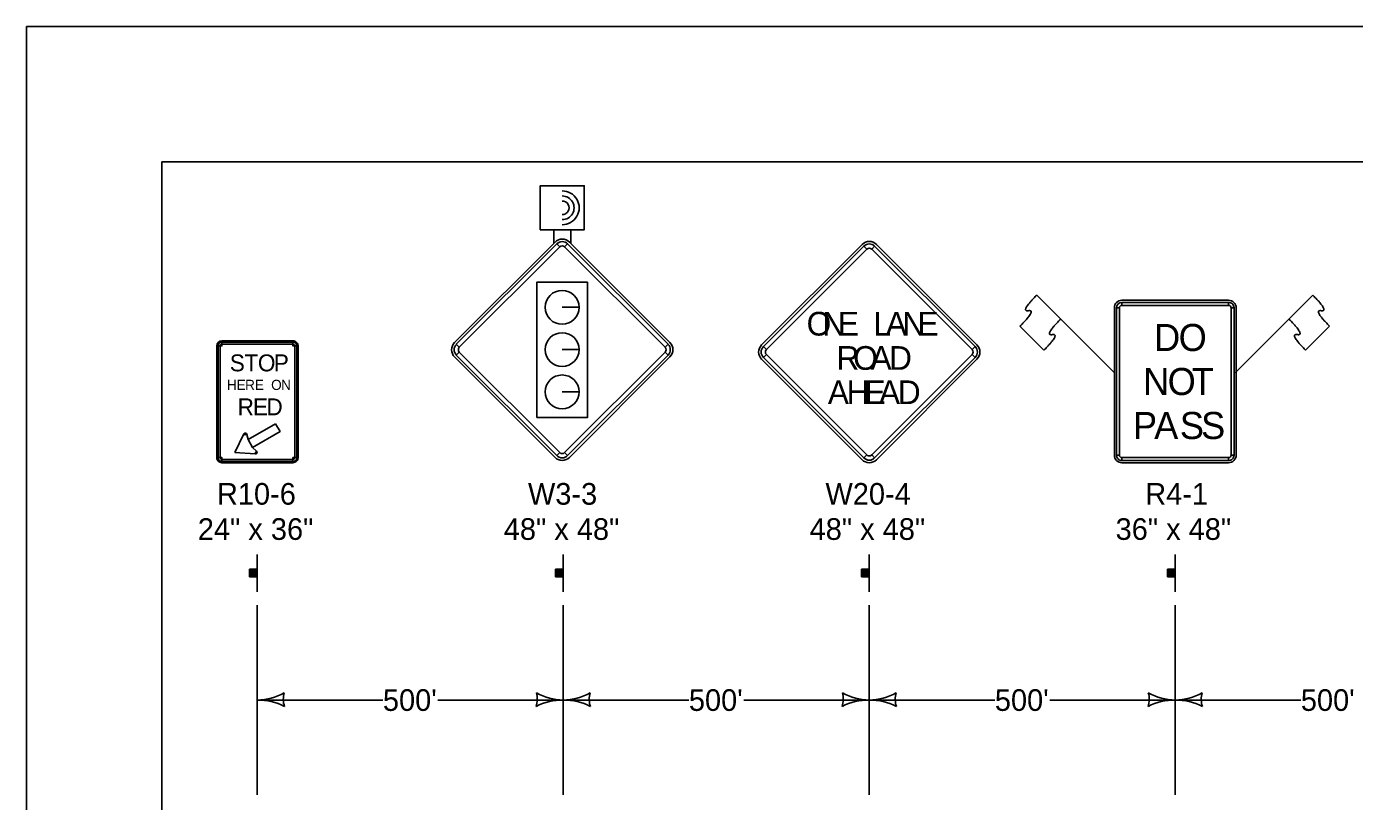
# Model space of a CAD drawing. Extents: x -2134934 to -2122394, y -2139046 to -2137036.
# Drawn here: x -2125529 to -2124549, y -2137608 to -2137036 of the extents above; entities that cross this region are included whole.
import ezdxf

# ---------------------------------------------------------------- set-up
doc = ezdxf.new("R2010")
doc.units = 0
for name, color, linetype in [('Barrier', 7, 'Continuous'), ('BridgeSuperStructureExisting', 7, 'Continuous'), ('Default', 7, 'Continuous'), ('TC_Barrier', 7, 'Continuous')]:
    doc.layers.add(name, color=color, linetype=linetype)

msp = doc.modelspace()

# ---------------------------------------------------------------- linework, layer by layer
at = {"layer": 'Barrier'}
for p, q in [((-2125139.05, -2137195.1), (-2125213.3, -2137269.35)), ((-2125137.72, -2137196.43), (-2125135.52, -2137198.64)), ((-2125131.98, -2137198.64), (-2125129.77, -2137196.43)), ((-2125054.2, -2137269.35), (-2125128.44, -2137195.1)), ((-2124912.21, -2137196.82), (-2124986.46, -2137271.07)), ((-2124910.89, -2137198.15), (-2124908.68, -2137200.36)), ((-2124905.14, -2137200.36), (-2124902.93, -2137198.15)), ((-2124827.36, -2137271.07), (-2124901.61, -2137196.82)), ((-2125121.34, -2137243.32), (-2125133.84, -2137243.32)), ((-2125133.84, -2137243.32), (-2125121.34, -2137243.32)), ((-2124725.87, -2137291.63), (-2124783.21, -2137234.33)), ((-2124783.21, -2137234.33), (-2124765.52, -2137252.01)), ((-2124641.5, -2137238.12), (-2124720.25, -2137238.12)), ((-2124720.25, -2137241.87), (-2124720.25, -2137239.68)), ((-2124641.5, -2137239.68), (-2124641.5, -2137241.87)), ((-2124636.58, -2137291.63), (-2124579.26, -2137234.32)), ((-2124579.26, -2137234.32), (-2124596.94, -2137252)), ((-2124725.87, -2137243.74), (-2124725.87, -2137352.49)), ((-2124724.31, -2137243.74), (-2124722.12, -2137243.74)), ((-2124639.62, -2137243.74), (-2124637.43, -2137243.74)), ((-2124635.87, -2137352.49), (-2124635.87, -2137243.74)), ((-2124777.9, -2137275), (-2124795.58, -2137257.33)), ((-2124584.56, -2137274.99), (-2124566.88, -2137257.31)), ((-2125388.89, -2137271.87), (-2125385.14, -2137271.87)), ((-2125387.95, -2137271.87), (-2125386.39, -2137271.87)), ((-2125385.14, -2137271.87), (-2125385.14, -2137268.12)), ((-2125385.14, -2137270.62), (-2125385.14, -2137269.05)), ((-2125332.64, -2137268.12), (-2125332.64, -2137271.87)), ((-2125332.64, -2137269.05), (-2125332.64, -2137270.62)), ((-2125332.64, -2137271.87), (-2125328.89, -2137271.87)), ((-2125331.39, -2137271.87), (-2125329.82, -2137271.87)), ((-2125209.76, -2137272.88), (-2125211.97, -2137270.67)), ((-2125055.53, -2137270.67), (-2125057.73, -2137272.88)), ((-2124982.92, -2137274.6), (-2124985.13, -2137272.39)), ((-2124828.69, -2137272.39), (-2124830.89, -2137274.6)), ((-2125213.3, -2137279.95), (-2125139.05, -2137354.2)), ((-2125211.97, -2137278.63), (-2125209.76, -2137276.42)), ((-2125121.34, -2137274.57), (-2125133.84, -2137274.57)), ((-2125133.84, -2137274.57), (-2125121.34, -2137274.57)), ((-2125128.44, -2137354.2), (-2125054.2, -2137279.95)), ((-2125057.73, -2137276.42), (-2125055.53, -2137278.63)), ((-2124986.46, -2137281.67), (-2124912.21, -2137355.92)), ((-2124985.13, -2137280.35), (-2124982.92, -2137278.14)), ((-2124901.61, -2137355.92), (-2124827.36, -2137281.67)), ((-2124830.89, -2137278.14), (-2124828.69, -2137280.35)), ((-2125121.34, -2137305.82), (-2125133.84, -2137305.82)), ((-2125133.84, -2137305.82), (-2125121.34, -2137305.82)), ((-2125369.03, -2137336.85), (-2125367.92, -2137337.43)), ((-2125367.92, -2137337.43), (-2125366.7, -2137337.16)), ((-2125360.42, -2137350.42), (-2125360.47, -2137351.67)), ((-2125359.58, -2137349.5), (-2125360.42, -2137350.42)), ((-2125135.52, -2137350.66), (-2125137.72, -2137352.87)), ((-2125129.77, -2137352.87), (-2125131.98, -2137350.66)), ((-2125385.14, -2137354.37), (-2125388.89, -2137354.37)), ((-2125386.39, -2137354.37), (-2125387.95, -2137354.37)), ((-2125385.14, -2137358.12), (-2125385.14, -2137354.37)), ((-2125385.14, -2137357.18), (-2125385.14, -2137355.62)), ((-2125328.89, -2137354.37), (-2125332.64, -2137354.37)), ((-2125332.64, -2137354.37), (-2125332.64, -2137358.12)), ((-2125332.64, -2137355.62), (-2125332.64, -2137357.18)), ((-2125329.82, -2137354.37), (-2125331.39, -2137354.37)), ((-2124908.68, -2137352.38), (-2124910.89, -2137354.59)), ((-2124902.93, -2137354.59), (-2124905.14, -2137352.38)), ((-2124722.12, -2137352.49), (-2124724.31, -2137352.49)), ((-2124720.25, -2137356.55), (-2124720.25, -2137354.37)), ((-2124720.25, -2137358.12), (-2124641.5, -2137358.12)), ((-2124641.5, -2137354.37), (-2124641.5, -2137356.55)), ((-2124637.43, -2137352.49), (-2124639.62, -2137352.49))]:
    msp.add_line(p, q, dxfattribs=at)
for points in [[(-2125429.46, -2137135.95), (-2124308.22, -2137135.95), (-2124308.22, -2137986.59), (-2125429.46, -2137986.59)], [(-2125137.72, -2137196.43), (-2125211.97, -2137270.67), (-2125209.76, -2137272.88), (-2125135.52, -2137198.64), (-2125137.72, -2137196.43)], [(-2125055.53, -2137270.67), (-2125129.77, -2137196.43), (-2125131.98, -2137198.64), (-2125057.73, -2137272.88), (-2125055.53, -2137270.67)], [(-2124910.89, -2137198.15), (-2124985.13, -2137272.39), (-2124982.92, -2137274.6), (-2124908.68, -2137200.36), (-2124910.89, -2137198.15)], [(-2124828.69, -2137272.39), (-2124902.93, -2137198.15), (-2124905.14, -2137200.36), (-2124830.89, -2137274.6), (-2124828.69, -2137272.39)], [(-2125115.02, -2137224.71), (-2125152.48, -2137224.71), (-2125152.48, -2137324.6), (-2125115.02, -2137324.6), (-2125115.02, -2137224.71)], [(-2124641.5, -2137239.68), (-2124720.25, -2137239.68), (-2124720.25, -2137241.87), (-2124641.5, -2137241.87), (-2124641.5, -2137239.68)], [(-2124724.31, -2137243.74), (-2124724.31, -2137352.49), (-2124722.12, -2137352.49), (-2124722.12, -2137243.74), (-2124724.31, -2137243.74)], [(-2124637.43, -2137352.49), (-2124637.43, -2137243.74), (-2124639.62, -2137243.74), (-2124639.62, -2137352.49), (-2124637.43, -2137352.49)], [(-2125385.14, -2137358.12), (-2125332.64, -2137358.12), (-2125332.64, -2137354.37), (-2125328.89, -2137354.37), (-2125328.89, -2137271.87), (-2125332.64, -2137271.87), (-2125332.64, -2137268.12), (-2125385.14, -2137268.12), (-2125385.14, -2137271.87), (-2125388.89, -2137271.87), (-2125388.89, -2137354.37), (-2125385.14, -2137354.37), (-2125385.14, -2137358.12)], [(-2125386.39, -2137271.87), (-2125386.39, -2137354.37), (-2125387.95, -2137354.37), (-2125387.95, -2137271.87), (-2125386.39, -2137271.87)], [(-2125332.64, -2137270.62), (-2125385.14, -2137270.62), (-2125385.14, -2137269.05), (-2125332.64, -2137269.05), (-2125332.64, -2137270.62)], [(-2125331.39, -2137354.37), (-2125331.39, -2137271.87), (-2125329.82, -2137271.87), (-2125329.82, -2137354.37), (-2125331.39, -2137354.37)], [(-2125211.97, -2137278.63), (-2125137.72, -2137352.87), (-2125135.52, -2137350.66), (-2125209.76, -2137276.42), (-2125211.97, -2137278.63)], [(-2125129.77, -2137352.87), (-2125055.53, -2137278.63), (-2125057.73, -2137276.42), (-2125131.98, -2137350.66), (-2125129.77, -2137352.87)], [(-2124985.13, -2137280.35), (-2124910.89, -2137354.59), (-2124908.68, -2137352.38), (-2124982.92, -2137278.14), (-2124985.13, -2137280.35)], [(-2124902.93, -2137354.59), (-2124828.69, -2137280.35), (-2124830.89, -2137278.14), (-2124905.14, -2137352.38), (-2124902.93, -2137354.59)], [(-2125345.52, -2137329.37), (-2125342.23, -2137335.05), (-2125362.54, -2137346.77), (-2125365.82, -2137341.09), (-2125345.52, -2137329.37)], [(-2125375.54, -2137350.49), (-2125360.47, -2137351.67), (-2125360.42, -2137350.42), (-2125359.58, -2137349.5), (-2125362.54, -2137346.77), (-2125365.82, -2137341.09), (-2125366.7, -2137337.16), (-2125367.92, -2137337.43), (-2125369.03, -2137336.85), (-2125375.54, -2137350.49)], [(-2125385.14, -2137355.62), (-2125332.64, -2137355.62), (-2125332.64, -2137357.18), (-2125385.14, -2137357.18), (-2125385.14, -2137355.62)], [(-2124720.25, -2137356.55), (-2124641.5, -2137356.55), (-2124641.5, -2137354.37), (-2124720.25, -2137354.37), (-2124720.25, -2137356.55)]]:
    msp.add_lwpolyline(points, close=True, dxfattribs=at)
for centre in [(-2125133.84, -2137243.32), (-2125133.84, -2137274.57), (-2125133.84, -2137305.82)]:
    msp.add_circle(centre, 12.5, dxfattribs=at)
for centre, radius, start, end in [((-2125133.75, -2137200.41), 7.5, 44.99999, 134.99974), ((-2124906.91, -2137202.12), 7.5, 44.99999, 134.99974), ((-2125133.75, -2137200.41), 5.62, 44.99999, 134.99974), ((-2125133.75, -2137200.41), 2.5, 44.99999, 134.99974), ((-2124906.91, -2137202.12), 5.62, 44.99999, 134.99974), ((-2124906.91, -2137202.12), 2.5, 44.99999, 134.99974), ((-2124720.25, -2137243.74), 5.62, 90.00021, 179.99985), ((-2124720.25, -2137243.74), 4.06, 90.00021, 179.99985), ((-2124720.25, -2137243.74), 1.87, 90.00021, 179.99985), ((-2124641.5, -2137243.74), 5.62, 0, 90.00021), ((-2124641.5, -2137243.74), 4.06, 0, 90.00021), ((-2124641.5, -2137243.74), 1.87, 0, 90.00021), ((-2125385.14, -2137271.87), 3.75, 90.00021, 179.99985), ((-2125385.14, -2137271.87), 2.81, 90.00021, 179.99985), ((-2125385.14, -2137271.87), 1.25, 90.00021, 179.99985), ((-2125332.64, -2137271.87), 3.75, 0, 90.00021), ((-2125332.64, -2137271.87), 2.81, 0, 90.00021), ((-2125332.64, -2137271.87), 1.25, 0, 90.00021), ((-2125207.99, -2137274.65), 7.5, 134.99974, 224.99995), ((-2125207.99, -2137274.65), 5.62, 134.99974, 224.99995), ((-2125207.99, -2137274.65), 2.5, 134.99974, 224.99995), ((-2125059.5, -2137274.65), 2.5, 315.00016, 44.9998), ((-2125059.5, -2137274.65), 5.62, 315.00016, 44.9998), ((-2125059.5, -2137274.65), 7.5, 315.00016, 44.9998), ((-2124981.15, -2137276.37), 7.5, 134.99974, 224.99995), ((-2124981.15, -2137276.37), 5.62, 134.99974, 224.99995), ((-2124832.66, -2137276.37), 5.62, 315.00016, 44.9998), ((-2124832.66, -2137276.37), 7.5, 315.00016, 44.9998), ((-2124981.15, -2137276.37), 2.5, 134.99974, 224.99995), ((-2124832.66, -2137276.37), 2.5, 315.00016, 44.9998), ((-2125367.92, -2137337.43), 1.25, 12.62232, 152.27557), ((-2125360.42, -2137350.42), 1.25, 267.72427, 47.37758), ((-2125133.75, -2137348.9), 2.5, 224.99995, 315.00016), ((-2125385.14, -2137354.37), 3.75, 179.99985, 270.00006), ((-2125385.14, -2137354.37), 2.81, 179.99985, 270.00006), ((-2125385.14, -2137354.37), 1.25, 179.99985, 270.00006), ((-2125332.64, -2137354.37), 3.75, 270.00006, 0.00027), ((-2125332.64, -2137354.37), 2.81, 270.00006, 0.00027), ((-2125332.64, -2137354.37), 1.25, 270.00006, 0.00027), ((-2125133.75, -2137348.9), 7.5, 224.99995, 315.00016), ((-2125133.75, -2137348.9), 5.62, 224.99995, 315.00016), ((-2124906.91, -2137350.62), 7.5, 224.99995, 315.00016), ((-2124906.91, -2137350.62), 5.62, 224.99995, 315.00016), ((-2124906.91, -2137350.62), 2.5, 224.99995, 315.00016), ((-2124720.25, -2137352.49), 5.62, 179.99985, 270.00006), ((-2124720.25, -2137352.49), 4.06, 179.99985, 270.00006), ((-2124720.25, -2137352.49), 1.87, 179.99985, 270.00006), ((-2124641.5, -2137352.49), 5.62, 270.00006, 0.00027), ((-2124641.5, -2137352.49), 4.06, 270.00006, 0.00027), ((-2124641.5, -2137352.49), 1.87, 270.00006, 0.00027)]:
    msp.add_arc(centre, radius, start, end, dxfattribs=at)
for points in [[(-2124795.58, -2137257.33), (-2124783.21, -2137244.95), (-2124795.58, -2137246.72), (-2124783.21, -2137234.33)], [(-2124566.88, -2137257.31), (-2124579.26, -2137244.93), (-2124566.88, -2137246.7), (-2124579.26, -2137234.32)], [(-2124765.52, -2137252.01), (-2124777.89, -2137264.4), (-2124765.53, -2137262.62), (-2124777.9, -2137275)], [(-2124596.94, -2137252), (-2124584.56, -2137264.38), (-2124596.93, -2137262.61), (-2124584.56, -2137274.99)]]:
    msp.add_open_spline(points, degree=2, dxfattribs=at)
at = {"layer": 'BridgeSuperStructureExisting'}
for p, q in [((-2125139.98, -2137186.06), (-2125139.98, -2137196.06)), ((-2125127.48, -2137186.06), (-2125127.48, -2137196.06)), ((-2125358.98, -2137425.94), (-2125358.98, -2137453.44)), ((-2125132.94, -2137425.94), (-2125132.94, -2137453.44)), ((-2124906.91, -2137425.94), (-2124906.91, -2137453.44)), ((-2124680.87, -2137425.94), (-2124680.87, -2137453.44)), ((-2125364.31, -2137436.8), (-2125364.31, -2137442.39)), ((-2125363.99, -2137442.39), (-2125363.99, -2137436.8)), ((-2125363.76, -2137436.8), (-2125363.76, -2137442.39)), ((-2125363.45, -2137442.39), (-2125363.45, -2137436.8)), ((-2125363.22, -2137436.8), (-2125363.24, -2137442.39)), ((-2125362.81, -2137442.39), (-2125362.79, -2137436.8)), ((-2125362.58, -2137436.8), (-2125362.58, -2137442.39)), ((-2125362.15, -2137442.39), (-2125362.15, -2137436.8)), ((-2125361.78, -2137436.8), (-2125361.78, -2137442.39)), ((-2125361.46, -2137442.39), (-2125361.44, -2137436.8)), ((-2125361.23, -2137436.8), (-2125361.23, -2137442.39)), ((-2125360.97, -2137442.39), (-2125360.97, -2137436.8)), ((-2125360.63, -2137436.8), (-2125360.63, -2137442.39)), ((-2125360.43, -2137442.39), (-2125360.43, -2137436.8)), ((-2125360.2, -2137436.8), (-2125360.2, -2137442.39)), ((-2125359.94, -2137442.39), (-2125359.94, -2137436.8)), ((-2125359.68, -2137436.8), (-2125359.68, -2137442.39)), ((-2125359.39, -2137442.39), (-2125359.39, -2137436.8)), ((-2125138.27, -2137436.8), (-2125138.27, -2137442.39)), ((-2125137.95, -2137442.39), (-2125137.95, -2137436.8)), ((-2125137.73, -2137436.8), (-2125137.73, -2137442.39)), ((-2125137.41, -2137442.39), (-2125137.41, -2137436.8)), ((-2125137.18, -2137436.8), (-2125137.2, -2137442.39)), ((-2125136.77, -2137442.39), (-2125136.75, -2137436.8)), ((-2125136.55, -2137436.8), (-2125136.55, -2137442.39)), ((-2125136.11, -2137442.39), (-2125136.11, -2137436.8)), ((-2125135.74, -2137436.8), (-2125135.74, -2137442.39)), ((-2125135.42, -2137442.39), (-2125135.4, -2137436.8)), ((-2125135.2, -2137436.8), (-2125135.2, -2137442.39)), ((-2125134.93, -2137442.39), (-2125134.93, -2137436.8)), ((-2125134.6, -2137436.8), (-2125134.6, -2137442.39)), ((-2125134.39, -2137442.39), (-2125134.39, -2137436.8)), ((-2125134.16, -2137436.8), (-2125134.16, -2137442.39)), ((-2125133.9, -2137442.39), (-2125133.9, -2137436.8)), ((-2125133.64, -2137436.8), (-2125133.64, -2137442.39)), ((-2125133.36, -2137442.39), (-2125133.36, -2137436.8)), ((-2124912.23, -2137436.8), (-2124912.23, -2137442.39)), ((-2124911.92, -2137442.39), (-2124911.92, -2137436.8)), ((-2124911.69, -2137436.8), (-2124911.69, -2137442.39)), ((-2124911.37, -2137442.39), (-2124911.37, -2137436.8)), ((-2124911.15, -2137436.8), (-2124911.17, -2137442.39)), ((-2124910.73, -2137442.39), (-2124910.72, -2137436.8)), ((-2124910.51, -2137436.8), (-2124910.51, -2137442.39)), ((-2124910.08, -2137442.39), (-2124910.08, -2137436.8)), ((-2124909.7, -2137436.8), (-2124909.7, -2137442.39)), ((-2124909.38, -2137442.39), (-2124909.37, -2137436.8)), ((-2124909.16, -2137436.8), (-2124909.16, -2137442.39)), ((-2124908.9, -2137442.39), (-2124908.9, -2137436.8)), ((-2124908.56, -2137436.8), (-2124908.56, -2137442.39)), ((-2124908.35, -2137442.39), (-2124908.35, -2137436.8)), ((-2124908.13, -2137436.8), (-2124908.13, -2137442.39)), ((-2124907.87, -2137442.39), (-2124907.87, -2137436.8)), ((-2124907.6, -2137436.8), (-2124907.6, -2137442.39)), ((-2124907.32, -2137442.39), (-2124907.32, -2137436.8)), ((-2124686.2, -2137436.8), (-2124686.2, -2137442.39)), ((-2124685.88, -2137442.39), (-2124685.88, -2137436.8)), ((-2124685.65, -2137436.8), (-2124685.65, -2137442.39)), ((-2124685.34, -2137442.39), (-2124685.34, -2137436.8)), ((-2124685.11, -2137436.8), (-2124685.13, -2137442.39)), ((-2124684.7, -2137442.39), (-2124684.68, -2137436.8)), ((-2124684.47, -2137436.8), (-2124684.47, -2137442.39)), ((-2124684.04, -2137442.39), (-2124684.04, -2137436.8)), ((-2124683.67, -2137436.8), (-2124683.67, -2137442.39)), ((-2124683.35, -2137442.39), (-2124683.33, -2137436.8)), ((-2124683.12, -2137436.8), (-2124683.12, -2137442.39)), ((-2124682.86, -2137442.39), (-2124682.86, -2137436.8)), ((-2124682.52, -2137436.8), (-2124682.52, -2137442.39)), ((-2124682.32, -2137442.39), (-2124682.32, -2137436.8)), ((-2124682.09, -2137436.8), (-2124682.09, -2137442.39)), ((-2124681.83, -2137442.39), (-2124681.83, -2137436.8)), ((-2124681.57, -2137436.8), (-2124681.57, -2137442.39)), ((-2124681.29, -2137442.39), (-2124681.29, -2137436.8)), ((-2125358.98, -2137603.44), (-2125358.98, -2137463.44)), ((-2125132.94, -2137603.44), (-2125132.94, -2137463.44)), ((-2124906.91, -2137603.44), (-2124906.91, -2137463.44)), ((-2124680.87, -2137603.44), (-2124680.87, -2137463.44)), ((-2125358.98, -2137533.44), (-2125266.21, -2137533.44)), ((-2125225.71, -2137533.44), (-2125132.94, -2137533.44)), ((-2125132.94, -2137533.44), (-2125040.18, -2137533.44)), ((-2124999.68, -2137533.44), (-2124906.91, -2137533.44)), ((-2124906.91, -2137533.44), (-2124814.14, -2137533.44)), ((-2124773.64, -2137533.44), (-2124680.87, -2137533.44)), ((-2124680.87, -2137533.44), (-2124588.1, -2137533.44))]:
    msp.add_line(p, q, dxfattribs=at)
for points in [[(-2125149.98, -2137186.06), (-2125149.98, -2137153.56), (-2125117.48, -2137153.56), (-2125117.48, -2137186.06)], [(-2125359.08, -2137442.39), (-2125359.08, -2137436.76), (-2125364.7, -2137436.76), (-2125364.7, -2137442.39)], [(-2125133.04, -2137442.39), (-2125133.04, -2137436.76), (-2125138.66, -2137436.76), (-2125138.66, -2137442.39)], [(-2124907, -2137442.39), (-2124907, -2137436.76), (-2124912.63, -2137436.76), (-2124912.63, -2137442.39)], [(-2124680.97, -2137442.39), (-2124680.97, -2137436.76), (-2124686.59, -2137436.76), (-2124686.59, -2137442.39)]]:
    msp.add_lwpolyline(points, close=True, dxfattribs=at)
for centre, radius, start, end in [((-2125133.72, -2137169.83), 12.5, 269.40414, 90.54446), ((-2125133.72, -2137169.83), 12.5, 269.40414, 90.54446), ((-2125133.72, -2137169.83), 8.75, 269.40414, 90.54446), ((-2125133.72, -2137169.83), 5, 269.40414, 90.54446), ((-2125359.74, -2137490.95), 42.5, 271.0176, 299.07249), ((-2125323.36, -2137532.82), 16.42, 163.26665, 198.73335), ((-2125168.56, -2137532.82), 16.42, 341.26665, 16.73335), ((-2125132.19, -2137490.95), 42.5, 240.92751, 268.9824), ((-2125133.7, -2137490.95), 42.5, 271.0176, 299.07249), ((-2125097.33, -2137532.82), 16.42, 163.26665, 198.73335), ((-2124942.53, -2137532.82), 16.42, 341.26665, 16.73335), ((-2124906.15, -2137490.95), 42.5, 240.92751, 268.9824), ((-2124907.66, -2137490.95), 42.5, 271.0176, 299.07249), ((-2124871.29, -2137532.82), 16.42, 163.26665, 198.73335), ((-2124716.49, -2137532.82), 16.42, 341.26665, 16.73335), ((-2124680.12, -2137490.95), 42.5, 240.92751, 268.9824), ((-2124681.63, -2137490.95), 42.5, 271.0176, 299.07249), ((-2124645.26, -2137532.82), 16.42, 163.26665, 198.73335), ((-2125358.25, -2137575.93), 42.5, 62.92751, 90.9824), ((-2125133.67, -2137575.93), 42.5, 89.0176, 117.07249), ((-2125132.22, -2137575.93), 42.5, 62.92751, 90.9824), ((-2124907.64, -2137575.93), 42.5, 89.0176, 117.07249), ((-2124906.18, -2137575.93), 42.5, 62.92751, 90.9824), ((-2124681.6, -2137575.93), 42.5, 89.0176, 117.07249), ((-2124680.14, -2137575.93), 42.5, 62.92751, 90.9824)]:
    msp.add_arc(centre, radius, start, end, dxfattribs=at)
at = {"layer": 'Default'}
msp.add_lwpolyline([(-2125529.46, -2137035.95), (-2122394.47, -2137035.95), (-2122394.47, -2139045.94), (-2125529.46, -2139045.94)], close=True, dxfattribs=at)
at = {"layer": 'TC_Barrier'}
for p, q in [((-2124795.58, -2137257.33), (-2124777.9, -2137275)), ((-2124566.88, -2137257.31), (-2124584.56, -2137274.99))]:
    msp.add_line(p, q, dxfattribs=at)
for points in [[(-2124783.21, -2137234.33), (-2124795.58, -2137246.72), (-2124783.21, -2137244.95), (-2124795.58, -2137257.33)], [(-2124579.26, -2137234.32), (-2124566.88, -2137246.7), (-2124579.26, -2137244.93), (-2124566.88, -2137257.31)], [(-2124765.52, -2137252.01), (-2124777.89, -2137264.4), (-2124765.53, -2137262.62), (-2124777.9, -2137275)], [(-2124596.94, -2137252), (-2124584.56, -2137264.38), (-2124596.93, -2137262.61), (-2124584.56, -2137274.99)]]:
    msp.add_open_spline(points, degree=2, dxfattribs=at)

# ---------------------------------------------------------------- texts
at = {"layer": 'Barrier'}
for s, height, p in [('O', 17.5, (-2124953.19, -2137264.18)), ('N', 17.5, (-2124941.42, -2137264.18)), ('E', 17.5, (-2124930.19, -2137264.18)), ('L', 17.5, (-2124903.94, -2137264.18)), ('A', 17.5, (-2124894.74, -2137264.18)), ('N', 17.5, (-2124882.48, -2137264.18)), ('E', 17.5, (-2124871.25, -2137264.18)), ('D', 20, (-2124696.5, -2137275.62)), ('O', 20, (-2124678.37, -2137275.62)), ('R', 17.5, (-2124931.09, -2137289.5)), ('O', 17.5, (-2124918.8, -2137289.5)), ('A', 17.5, (-2124905.96, -2137289.5)), ('D', 17.5, (-2124892.3, -2137289.5)), ('S', 12.5, (-2125379.33, -2137290.62)), ('T', 12.5, (-2125368.57, -2137290.62)), ('O', 12.5, (-2125358.58, -2137290.62)), ('P', 12.5, (-2125346.84, -2137290.62)), ('N', 20, (-2124704.62, -2137308.12)), ('O', 20, (-2124686.5, -2137308.12)), ('T', 20, (-2124668.68, -2137308.12)), ('H', 7.5, (-2125381.41, -2137304.37)), ('E', 7.5, (-2125374.26, -2137304.37)), ('R', 7.5, (-2125368, -2137304.37)), ('E', 7.5, (-2125360.85, -2137304.37)), ('O', 7.5, (-2125348.78, -2137304.37)), ('N', 7.5, (-2125341.4, -2137304.37)), ('A', 17.5, (-2124937.52, -2137314.81)), ('H', 17.5, (-2124923.66, -2137314.81)), ('E', 17.5, (-2124910.44, -2137314.81)), ('A', 17.5, (-2124899.73, -2137314.81)), ('D', 17.5, (-2124885.86, -2137314.81)), ('R', 12.5, (-2125373.57, -2137323.12)), ('E', 12.5, (-2125362.25, -2137323.12)), ('D', 12.5, (-2125352.28, -2137323.12)), ('P', 20, (-2124712.14, -2137340.62)), ('A', 20, (-2124696.45, -2137340.62)), ('S', 20, (-2124677.48, -2137340.62)), ('S', 20, (-2124661.79, -2137340.62)), ('R10-6', 16, (-2125388.81, -2137389.12)), ('W3-3', 16, (-2125159.04, -2137389.12)), ('W20-4', 16, (-2124939.27, -2137389.12)), ('R4-1', 16, (-2124703.04, -2137389.12)), ('24" x 36"', 16, (-2125402.95, -2137415.12)), ('48" x 48"', 16, (-2125176.92, -2137415.12)), ('48" x 48"', 16, (-2124950.98, -2137415.12)), ('36" x 48"', 16, (-2124724.94, -2137415.12))]:
    msp.add_text(s, height=height, dxfattribs=at).set_placement(p)
at = {"layer": 'BridgeSuperStructureExisting'}
for p in [(-2125266.21, -2137541.44), (-2125040.18, -2137541.44), (-2124814.14, -2137541.44), (-2124588.1, -2137541.44)]:
    msp.add_text("500'", height=16, dxfattribs=at).set_placement(p)

doc.saveas('drawing.dxf')
